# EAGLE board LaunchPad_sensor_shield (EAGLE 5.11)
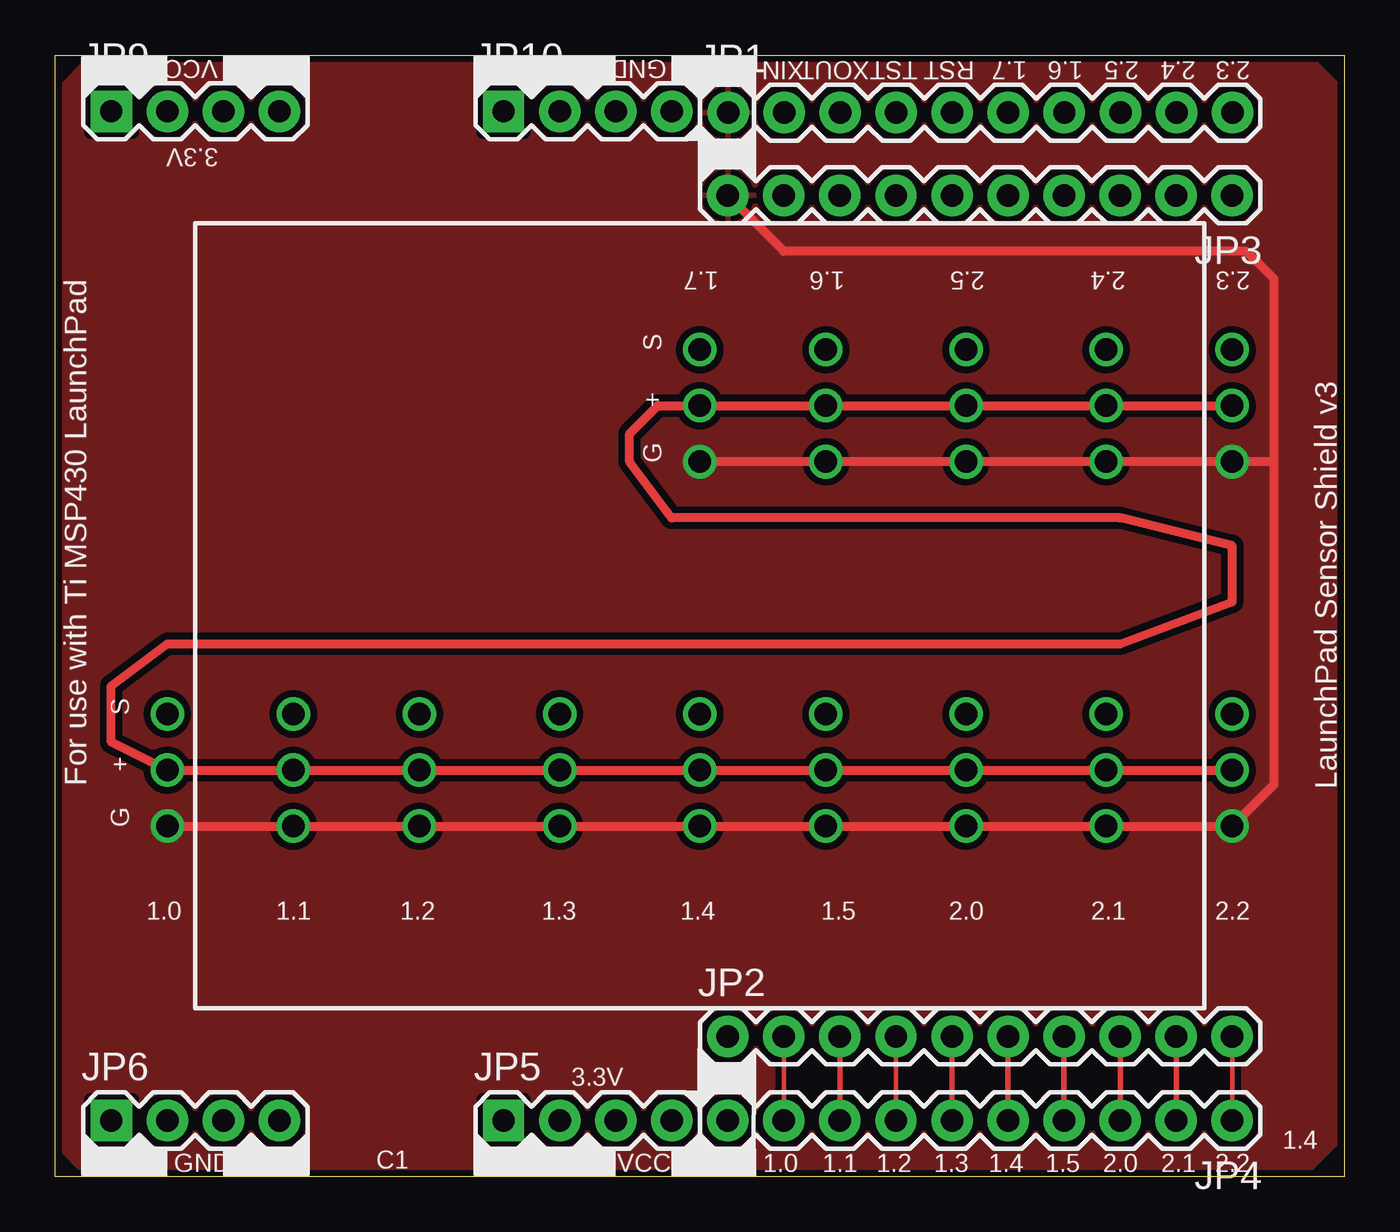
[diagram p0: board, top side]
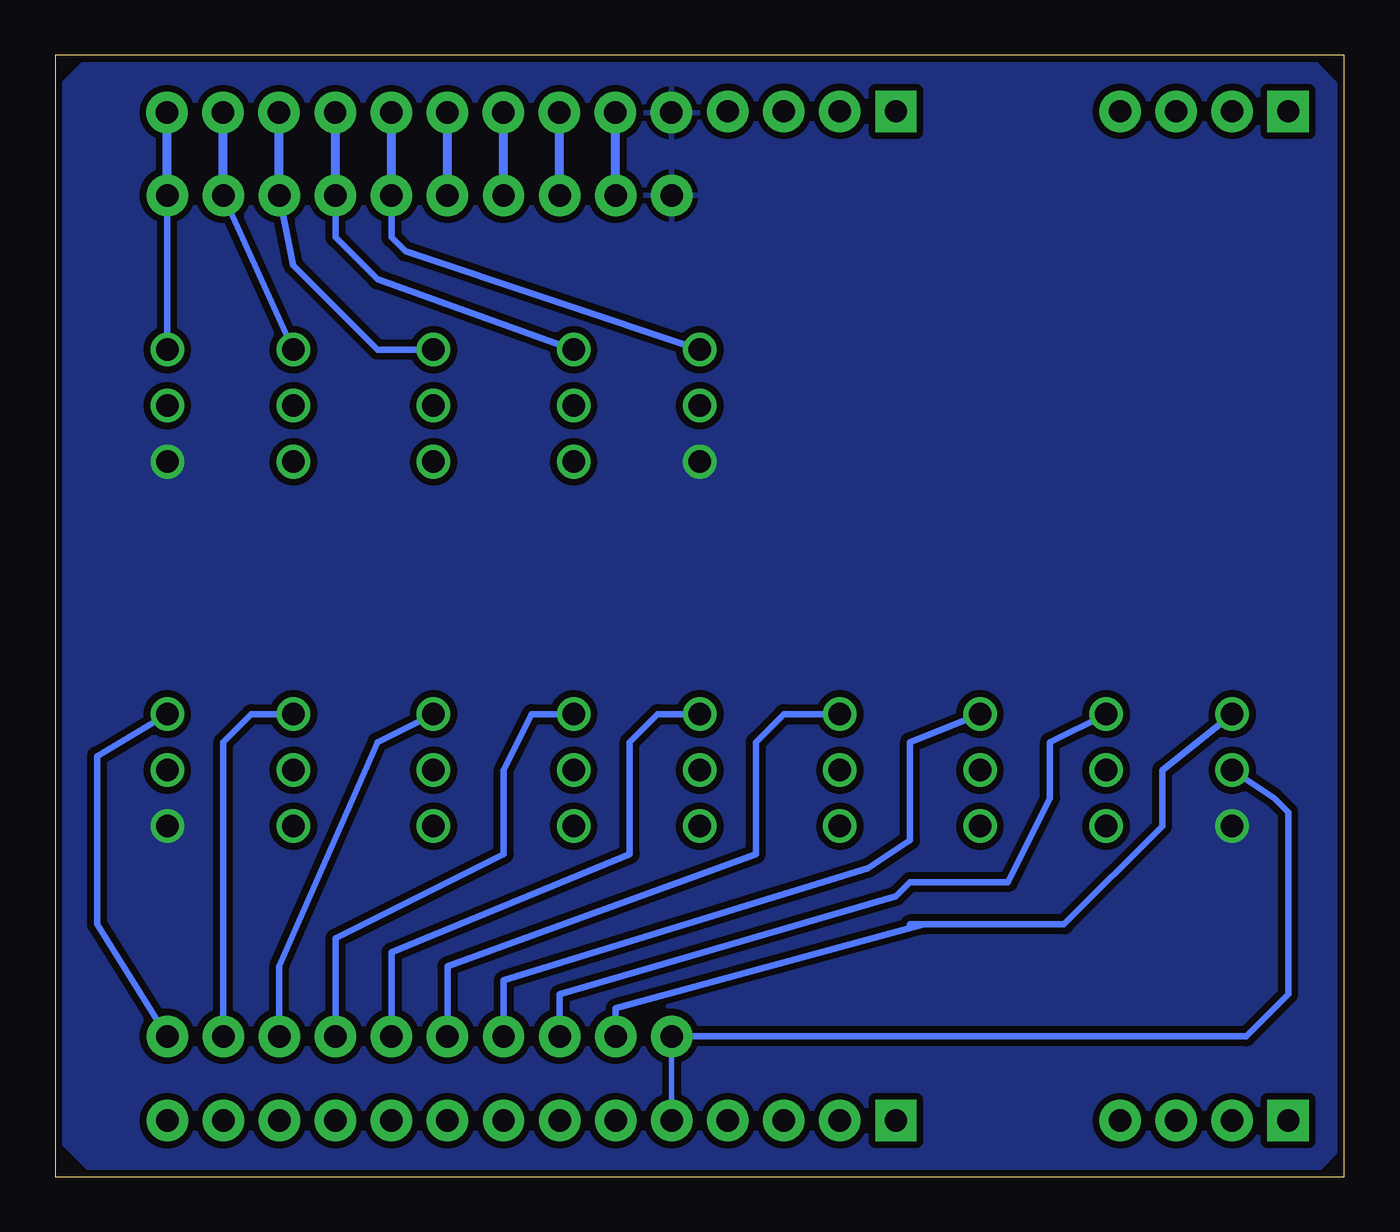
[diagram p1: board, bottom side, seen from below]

Size 58.42 x 50.8 mm. Coordinates in mm from the lower left corner, seen from the top.
Outline: 0,0 0,50.8 58.42,50.8 58.42,0 0,0
Copper layers (1*16): Top 0.035mm / dielectric 1.5mm / Bottom 0.035mm
Design rules "SparkFun": minimum track width 8mil, minimum drill 20mil, track to track 8mil, track to pad 8mil, pad to pad 8mil, via to via 8mil, smd to smd 8mil, copper to edge 10mil, drill to drill 8mil, minimum pad ring 12mil, minimum via ring 10mil, stop-mask expansion 4mil, vias tented up to drill 25mil, thermal gap 10mil

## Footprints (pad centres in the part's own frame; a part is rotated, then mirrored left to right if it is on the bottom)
1X10 = drill 1.016 pad 1.88 round: 1 0,0; 2 2.54,0; 3 5.08,0; 4 7.62,0; 5 10.16,0; 6 12.7,0; 7 15.24,0; 8 17.78,0; 9 20.32,0; 10 22.86,0
1X04 = drill 1.016 pad 1.88 square: 1 0,0 | drill 1.016 pad 1.88 round: 2 2.54,0; 3 5.08,0; 4 7.62,0

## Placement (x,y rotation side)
JP1  M10"  [1X10]  30.49,48.2 0 top
JP2  M10"  [1X10]  30.48,6.35 0 top
JP3  M10"  [1X10]  53.34,44.45 180 top
JP4  M10"  [1X10]  53.34,2.54 180 top
JP5  [1X04]  20.32,2.54 0 top
JP6  [1X04]  2.54,2.54 0 top
JP9  [1X04]  2.54,48.26 0 top
JP10  [1X04]  20.32,48.26 0 top
U$1  BREADBOARDMINI  [BREADBOARD-MINI]  6.35,7.62 0 top

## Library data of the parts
JP1-JP6 JP9 JP10 U$1 = SparkFun

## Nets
GND: JP1.1 JP3.10
N$308: JP2.10 JP4.1
RST/SBWTDIO: JP1.5
S$1: JP3.8
S$2: JP3.6
S$3: JP1.7
S$4: JP1.9
S$5: JP2.3 JP4.8
S$7: JP2.5 JP4.6
S$8: JP3.2
S$9: JP3.4
S$13: JP3.3
S$16: JP2.7 JP4.4
S$20: JP3.5
S$22: JP2.4 JP4.7
S$24: JP2.6 JP4.5
S$26: JP2.9 JP4.2
S$37: JP2.2 JP4.9
S$56: JP2.8 JP4.3
S$58: JP3.1
TEST: JP3.7
VCC: JP2.1 JP4.10
XIN: JP3.9
XOUT: JP1.3

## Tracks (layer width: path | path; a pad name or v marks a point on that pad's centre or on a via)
GND  (via drill 1.02 pad 1.52)
  Top 0.406: JP3.10 33.02,41.91 53.98,41.91 55.24,40.64 55.24,32.38 | v5.08,15.88 v53.34,15.88 55.24,17.78 55.24,32.38 | v29.21,32.38 v53.34,32.38 55.24,32.38
  pour Top (isolate 0.305): 1.75,50.81 56.71,50.81 58.46,49.06 58.46,1.96 56.5,0 1.55,0 0,1.55 0,49.06
  pour Bottom (isolate 0.305): 1.75,50.81 56.71,50.81 58.46,49.06 58.46,1.96 56.5,0 1.55,0 0,1.55 0,49.06
N$308  (via drill 1.02 pad 1.52)
  Top 0.203: JP4.1 JP2.10
  Bottom 0.305: JP2.10 56.52,11.43 56.52,19.05 v53.34,20.95
RST/SBWTDIO
  Top 0.254: JP1.5 40.64,48.18
S$1
  Bottom 0.406: JP3.8 35.56,48.26
S$2
  Top 0.254: JP3.6 40.65,44.46
  Bottom 0.406: JP3.6 40.64,48.26
S$3
  Top 0.254: JP1.7 45.72,48.18
S$4
  Top 0.254: JP1.9 50.8,48.18
S$5  (via drill 1.02 pad 1.52)
  Top 0.254: JP2.3 JP4.8
  Bottom 0.305: JP2.3 35.56,8.26 20.32,12.7 19.68,13.34 15.24,13.34 13.34,17.14 13.34,19.68 v10.79,20.95
S$6  (via drill 1.02 pad 1.52)
  other vias: 16.51,18.41
S$7  (via drill 1.02 pad 1.52)
  Top 0.254: JP2.5 JP4.6
  Bottom 0.305: JP2.5 40.64,9.53 26.67,14.61 26.67,19.68 25.4,20.95 v22.86,20.95
S$8  (via drill 1.02 pad 1.52)
  Top 0.254: JP3.2 50.81,44.46
  Bottom 0.305: v47.62,37.47 JP3.2
  Bottom 0.406: JP3.2 50.8,48.26
S$9  (via drill 1.02 pad 1.52)
  Top 0.254: JP3.4 45.73,44.46
  Bottom 0.305: v34.92,37.47 43.81,40.64 45.72,42.55 JP3.4
  Bottom 0.406: JP3.4 45.72,48.26
S$10  (via drill 1.02 pad 1.52)
  other vias: 41.27,34.92
S$11  (via drill 1.02 pad 1.52)
  other vias: 34.92,34.92
S$12  (via drill 1.02 pad 1.52)
  other vias: 29.21,18.41
S$13  (via drill 1.02 pad 1.52)
  Top 0.254: JP3.3 48.27,44.46
  Bottom 0.305: v41.27,37.47 43.81,37.47 47.62,41.27 JP3.3
  Bottom 0.406: JP3.3 48.26,48.26
S$15  (via drill 1.02 pad 1.52)
  other vias: 47.62,34.92
S$16  (via drill 1.02 pad 1.52)
  Top 0.254: JP4.4 JP2.7
  Bottom 0.305: JP2.7 45.72,10.79 38.1,14.61 38.1,18.41 36.83,20.95 v34.92,20.95
S$17  (via drill 1.02 pad 1.52)
  other vias: 34.92,32.38
S$18  (via drill 1.02 pad 1.52)
  other vias: 41.27,32.38
S$19  (via drill 1.02 pad 1.52)
  other vias: 47.62,32.38
S$20  (via drill 1.02 pad 1.52)
  Top 0.254: JP3.5 43.19,44.46
  Bottom 0.305: v29.21,37.47 42.55,41.91 43.18,42.55 JP3.5
  Bottom 0.406: JP3.5 43.18,48.26
S$21  (via drill 1.02 pad 1.52)
  other vias: 10.79,18.41
S$22  (via drill 1.02 pad 1.52)
  Top 0.203: JP2.4 JP4.7
  Bottom 0.305: JP2.4 38.1,8.89 21.59,13.97 19.68,15.24 19.68,19.68 v16.51,20.95
S$23  (via drill 1.02 pad 1.52)
  other vias: 10.79,15.88
S$24  (via drill 1.02 pad 1.52)
  Top 0.254: JP2.6 JP4.5
  Bottom 0.305: JP2.6 43.18,10.16 32.38,14.61 32.38,19.68 31.11,20.95 v29.21,20.95
S$25  (via drill 1.02 pad 1.52)
  other vias: 41.27,18.41
S$26  (via drill 1.02 pad 1.52)
  Top 0.254: JP4.2 JP2.9
  Bottom 0.305: JP2.9 50.8,19.68 49.53,20.95 v47.62,20.95
S$27  (via drill 1.02 pad 1.52)
  other vias: 16.51,15.88
S$28  (via drill 1.02 pad 1.52)
  other vias: 22.86,15.88
S$29  (via drill 1.02 pad 1.52)
  other vias: 29.21,15.88
S$30  (via drill 1.02 pad 1.52)
  other vias: 34.92,15.88
S$31  (via drill 1.02 pad 1.52)
  other vias: 41.27,15.88
S$32  (via drill 1.02 pad 1.52)
  other vias: 47.62,15.88
S$37  (via drill 1.02 pad 1.52)
  Top 0.203: JP2.2 JP4.9
  Bottom 0.305: JP2.2 33.02,7.62 19.05,11.43 | 19.05,11.43 19.68,11.43 | 19.05,11.43 12.7,11.43 8.26,15.88 8.26,18.41 v5.08,20.95
S$50  (via drill 1.02 pad 1.52)
  other vias: 22.86,18.41
S$55  (via drill 1.02 pad 1.52)
  other vias: 34.92,18.41
S$56  (via drill 1.02 pad 1.52)
  Top 0.254: JP4.3 JP2.8
  Bottom 0.305: JP2.8 48.26,9.53 43.81,19.68 v41.27,20.95
S$57  (via drill 1.02 pad 1.52)
  other vias: 47.62,18.41
S$58  (via drill 1.02 pad 1.52)
  Top 0.254: JP3.1 53.35,44.46
  Bottom 0.305: v53.34,37.47 JP3.1
  Bottom 0.406: JP3.1 53.34,48.26
TEST
  Top 0.254: JP3.7 38.11,44.46
  Bottom 0.406: JP3.7 38.1,48.26
VCC  (via drill 1.02 pad 1.52)
  Top 0.406: v53.34,18.41 v5.08,18.41 2.54,19.68 2.54,22.23 5.08,24.13 48.26,24.13 53.34,26.04 53.34,28.57 48.26,29.84 27.94,29.84 26.04,32.38 26.04,33.66 27.3,34.92 v29.21,34.92 v53.34,34.92
  Bottom 0.254: JP2.1 JP4.10
  Bottom 0.305: v5.08,18.41 3.17,17.14 2.54,16.51 2.54,8.26 4.45,6.35 JP2.1
XIN
  Top 0.254: JP3.9 33.03,44.46
  Bottom 0.406: JP3.9 33.02,48.26
XOUT
  Top 0.203: JP1.3 35.56,48.26

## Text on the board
tPlace: VCC | GND | XIN | XOUT | TST | RST | 1.7 | 1.6 | 2.5 | 2.4 | 2.3 | 3.3V | For use with Ti MSP430 LaunchPad | 1.7 | 1.6 | 2.5 | 2.4 | 2.3 | S | LaunchPad Sensor Shield v3 | + | G | S | + | G | 1.0 | 1.1 | 1.2 | 1.3 | 1.4 | 1.5 | 2.0 | 2.1 | 2.2 | 3.3V | VCC | 1.4 | GND | C1 | 1.0 | 1.1 | 1.2 | 1.3 | 1.4 | 1.5 | 2.0 | 2.1 | 2.2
